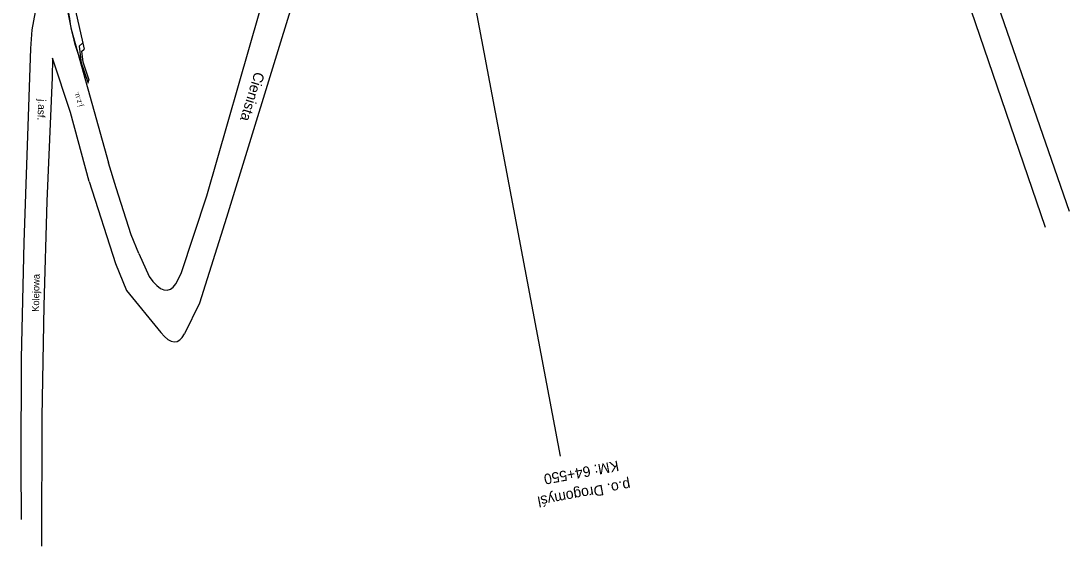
# Model space of a CAD drawing. Extents: x 6541740 to 6566395, y 5525066 to 5530361.
# Drawn here: x 6556400.7 to 6556525.8, y 5525925.2 to 5525987.9 of the extents above; entities that cross this region are included whole.
import ezdxf

# ---------------------------------------------------------------- set-up
doc = ezdxf.new("R2010")
doc.units = 0
for name, color, linetype in [('TOR_PS_OPIS_T-numeracja torow i rozjazdow', 7, 'Continuous'), ('TOR_PS_OPIS_T-symbole geometrii', 7, 'Continuous'), ('TOR_PS_T-wypelnienia', 7, 'Continuous')]:
    doc.layers.add(name, color=color, linetype=linetype)

msp = doc.modelspace()

# ---------------------------------------------------------------- linework, layer by layer
at = {"layer": 'TOR_PS_OPIS_T-numeracja torow i rozjazdow'}
msp.add_lwpolyline([(6556465.13, 5525935.87), (6556449.87, 5526016.63), (6556449.87, 5526016.63), (6556449.87, 5526016.63)], dxfattribs=at)
at = {"layer": 'TOR_PS_OPIS_T-symbole geometrii'}
for p, q in [((6556407.21, 5525989.07), (6556408.09, 5525985.21)), ((6556407.66, 5525984.86), (6556408.08, 5525985.2)), ((6556407.66, 5525984.86), (6556407.92, 5525982.83)), ((6556408.09, 5525985.21), (6556408.24, 5525984.48)), ((6556407.39, 5525984.39), (6556408.72, 5525980.45)), ((6556407.93, 5525984.23), (6556408.24, 5525984.48)), ((6556407.93, 5525984.23), (6556408.09, 5525982.97)), ((6556408.09, 5525982.97), (6556408.81, 5525980.85)), ((6556408.81, 5525980.85), (6556408.7, 5525980.53))]:
    msp.add_line(p, q, dxfattribs=at)
msp.add_ellipse((6556408.12, 5525987.53), major_axis=(-1.12, 5.9), ratio=0.25, start_param=1.194409, end_param=2.083908, dxfattribs=at)
at = {"layer": 'TOR_PS_T-wypelnienia'}
for p, q in [((6556512.48, 5526003.7), (6556525.81, 5525965.13)), ((6556523.01, 5525963.19), (6556510.16, 5526000.82)), ((6556434.7, 5525995.11), (6556425.26, 5525964.4)), ((6556405.33, 5525993.59), (6556406.72, 5525986.89)), ((6556402.05, 5525986.82), (6556403.02, 5525991.93)), ((6556422.91, 5525966.97), (6556429.23, 5525989.04)), ((6556401.91, 5525984.59), (6556402.05, 5525986.82)), ((6556406.72, 5525986.89), (6556411.15, 5525970.92)), ((6556401.08, 5525961.39), (6556401.91, 5525984.59)), ((6556404.49, 5525983.43), (6556404.42, 5525981.12)), ((6556406.64, 5525976.92), (6556404.49, 5525983.43)), ((6556404.42, 5525981.12), (6556403.82, 5525966.35)), ((6556408.86, 5525968.68), (6556406.64, 5525976.92)), ((6556408.86, 5525968.68), (6556411.99, 5525958.89)), ((6556403.82, 5525966.35), (6556403.44, 5525953.83)), ((6556419.85, 5525957.71), (6556422.91, 5525966.97)), ((6556425.26, 5525964.4), (6556422.03, 5525954.15)), ((6556400.76, 5525947.58), (6556401.08, 5525961.39)), ((6556419.19, 5525956.48), (6556419.85, 5525957.71)), ((6556403.44, 5525953.83), (6556403.21, 5525940.6)), ((6556422.03, 5525954.15), (6556420.24, 5525950.51)), ((6556400.72, 5525934.88), (6556400.76, 5525947.58)), ((6556403.21, 5525940.6), (6556403.16, 5525925.15)), ((6556400.78, 5525928.33), (6556400.72, 5525934.88))]:
    msp.add_line(p, q, dxfattribs=at)
for points in [[(6556414.79, 5525960.08), (6556413.88, 5525962.34), (6556412.06, 5525967.94), (6556411.15, 5525970.92)], [(6556414.79, 5525960.08), (6556416.01, 5525957.36), (6556416.01, 5525957.36)], [(6556411.99, 5525958.89), (6556413.32, 5525955.69), (6556417.42, 5525950.64)]]:
    msp.add_lwpolyline(points, dxfattribs=at)
for centre, major_axis, start_param, end_param in [((6556415.36, 5525971.09), (-2.91, 15.37), 2.627221, 3.412235), ((6556416.45, 5525964.24), (-2.78, 14.68), 2.705396, 3.458735)]:
    msp.add_ellipse(centre, major_axis=major_axis, ratio=0.25, start_param=start_param, end_param=end_param, dxfattribs=at)

# ---------------------------------------------------------------- texts
at = {"layer": 'TOR_PS_OPIS_T-numeracja torow i rozjazdow'}
for s, p in [('KM: 64+550', (6556471.95, 5525935.37)), ('p.o. Drogomyśl', (6556473.34, 5525933.09))]:
    msp.add_text(s, height=1.25, rotation=190.5522, dxfattribs=at).set_placement(p)
at = {"layer": 'TOR_PS_T-wypelnienia'}
for s, height, rotation, p in [('Cienista', 1.247, 252.9137, (6556428.63, 5525981.87)), ('j.asf.', 0.895, 267.214, (6556402.8, 5525978.54)), ('j.z.u.', 0.633, 108.0122, (6556408.1, 5525977.73)), ('Kolejowa', 0.832, 89.0496, (6556402.87, 5525953.12))]:
    msp.add_text(s, height=height, rotation=rotation, dxfattribs=at).set_placement(p)

doc.saveas('drawing.dxf')
